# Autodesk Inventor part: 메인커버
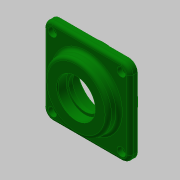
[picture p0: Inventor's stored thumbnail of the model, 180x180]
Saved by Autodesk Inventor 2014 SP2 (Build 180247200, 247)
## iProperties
Created: 2018-09
Part Number: 메인커버
Material: 알루미늄 6061
Document SubType Name: Modeling
Designer: mduedu
Density: 2.71 g/cm^3
Appearance: 진녹색
Mass: 178.463 g
Surface Area: 197.883 cm^2
Volume: 65.8536 cm^3
Author: mduedu
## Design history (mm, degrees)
sketch "스케치1"
  geometry: L1 (-40, -40)-(40, -40); L2 (40, -40)-(40, 40); L3 (40, 40)-(-40, 40); L4 (-40, 40)-(-40, -40); L5 (-40, -40)-(40, 40); L6 (40, -40)-(-40, 40); 1 further point
  constraints: 12 end point, 2 midpoint, 2 parallel, 1 horizontal, 1 perpendicular
  dimensions: "d0" = 80 distance of L3.end L2.end; "d1" = 80 distance of L2.end L1.end
extrude "돌출1" new body sketch "스케치1" distance "d2" = 7; taper "d3" = 0 deg
sketch "스케치2"
  geometry: C1 r 30 at (0, 0); 1 further point
  constraints: 1 centre point, 1 coincident
  dimensions: "d4" = 60 diameter of C1
extrude "돌출2" join sketch "스케치2" distance "d5" = 10; taper "d6" = 0 deg
sketch "스케치3"
  geometry: C1 r 32.5 at (0, 0); 1 further point
  constraints: 1 centre point, 1 coincident
  dimensions: "d7" = 65 diameter of C1
extrude "돌출3" join sketch "스케치3" distance "d8" = 9; taper "d9" = 0 deg
sketch "스케치4"
  geometry: L1 (-32.5, -9)-(32.5, -9) reference; L2 (30, 17)-(-30, 17) reference; L3 (0, 17)-(0, -9); L4 (0, -9)-(23.5, -9); L5 (23.5, -9)-(23.5, 5); L6 (23.5, 5)-(0, 5); L7 (0, 5)-(0, -9); L8 (0, 5)-(15, 5); L9 (15, 5)-(15, 8.7); L10 (15, 8.7)-(0, 8.7); L11 (0, 8.7)-(0, 5); L12 (0, 8.7)-(17.5, 8.7); L13 (17.5, 8.7)-(17.5, 17); L14 (17.5, 17)-(0, 17); L15 (0, 17)-(0, 8.7); 1 further point
  constraints: 26 end point, 6 parallel, 3 horizontal, 3 perpendicular, 2 midpoint, 1 point on line
  dimensions: "d10" = 14 distance of L4.end L5.end; "d12" = 8.3 distance of L12.end L13.end; "d13" = 35 diameter of L13 L3; "d14" = 30 diameter of L9 L3; "d15" = 47 diameter of L5 L3
revolve "회전1" sketch "스케치4" stored, may be unused: angle "d16" = 90 deg
fillet "모깎기1" dims "d17" = 8
fillet "모깎기2" dims "d18" = 3
fillet "모깎기3" dims "d19" = 3
chamfer "모따기1" distance "d20" = 0.8; stored, may be unused: second distance "d21" = 2, angle "d22" = 30 deg
chamfer "모따기2" distance "d23" = 1; stored, may be unused: second distance "d24" = 2, angle "d25" = 30 deg
fillet "모깎기4" dims "d26" = 0.3
sketch "스케치5"
  geometry: A1 r 8 centre (-32, 32) between (-32, 40) and (-40, 32) reference; A2 r 8 centre (-32, -32) between (-40, -32) and (-32, -40) reference; A3 r 8 centre (32, -32) between (32, -40) and (40, -32) reference; A4 r 8 centre (32, 32) between (40, 32) and (32, 40) reference; 5 further points
  constraints: 4 coincident
hole "구멍1" sketch "스케치5" at (-32, 32), (32, 32), (32, -32), (-32, -32) diameter "d27" = 4.5; stored, may be unused: countersink angle "d31" = 90 deg, drill point angle "d33" = 118 deg; dims "d28" = 6, "d29" = 8, "d30" = 4.4, "d32" = 8
node "솔리드1"
